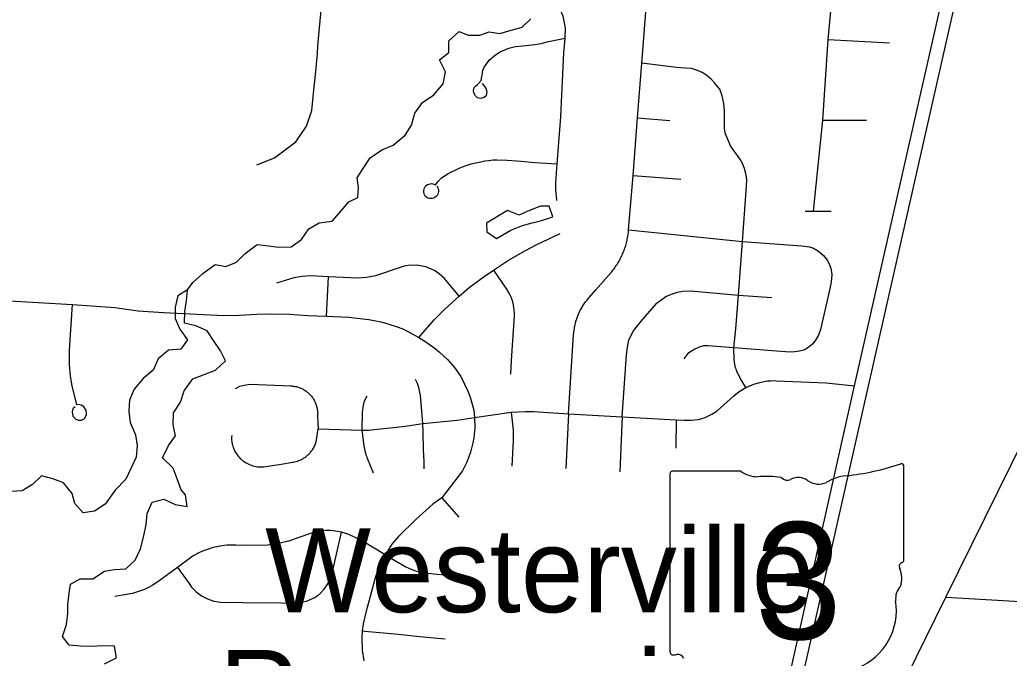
# Model space of a CAD drawing. Extents: x 0 to 34, y 0 to 22.
# Drawn here: x 8.488 to 9.603, y 8.895 to 9.615 of the extents above; entities that cross this region are included whole.
import ezdxf

# ---------------------------------------------------------------- set-up
doc = ezdxf.new("R2010")
doc.units = 0
for name, color, linetype in [('GM_X_County_Road', 7, 'Continuous'), ('GM_X_Minor_Lake', 7, 'Continuous'), ('GM_X_Minor_Lake_Text', 7, 'Continuous'), ('GM_X_Minor_River', 7, 'Continuous'), ('GM_X_Rail_Line', 7, 'Continuous'), ('GM_X_State_Location', 7, 'Continuous'), ('GM_X_State_Route', 7, 'Continuous'), ('GM_X_State_Shield', 7, 'Continuous'), ('GM_X_Township_Road', 7, 'Continuous')]:
    doc.layers.add(name, color=color, linetype=linetype)

msp = doc.modelspace()

# ---------------------------------------------------------------- linework, layer by layer
at = {"layer": 'GM_X_County_Road'}
msp.add_lwpolyline([(9.2983, 8.492), (9.3206, 8.5378), (9.4763, 8.8512), (9.532, 8.9642), (9.6643, 9.2319), (9.7654, 9.4338), (9.7887, 9.4806), (9.823, 9.5499), (9.8784, 9.6595), (9.9012, 9.7059), (9.9498, 9.7963), (10.0655, 10.0271), (10.1462, 10.1841)], dxfattribs=at)
at = {"layer": 'GM_X_Minor_Lake'}
for points in [[(9.0846, 9.3914), (9.0889, 9.3928), (9.0847, 9.4049), (9.0749, 9.4049), (9.0609, 9.3992), (9.0511, 9.3946), (9.0378, 9.3999)], [(9.0378, 9.3999), (9.014, 9.3858), (9.0144, 9.376), (9.0254, 9.3684), (9.0416, 9.3779), (9.0549, 9.3829), (9.0655, 9.3859), (9.0761, 9.3886), (9.0846, 9.3914)], [(8.6699, 9.0851), (8.6654, 9.0976), (8.661, 9.1098), (8.6489, 9.1212), (8.6558, 9.1352), (8.6635, 9.1462), (8.6609, 9.1583), (8.6613, 9.172), (8.669, 9.1841), (8.6732, 9.1969), (8.6831, 9.2101), (8.696, 9.215), (8.7086, 9.2199), (8.72, 9.2304), (8.7144, 9.2418), (8.7072, 9.2525), (8.6994, 9.2643), (8.6865, 9.27), (8.6737, 9.2731), (8.6742, 9.286), (8.6761, 9.2985), (8.677, 9.3106), (8.6663, 9.3039), (8.6632, 9.291), (8.6631, 9.2781), (8.6684, 9.2663), (8.677, 9.2542), (8.6694, 9.2436), (8.6557, 9.2425), (8.6439, 9.2327), (8.6382, 9.2202), (8.6272, 9.2108), (8.6169, 9.1988), (8.6115, 9.1863), (8.611, 9.1738), (8.6125, 9.1609), (8.6184, 9.1472), (8.6203, 9.135), (8.619, 9.1221), (8.6137, 9.11), (8.6075, 9.0972), (8.5954, 9.0847), (8.5843, 9.0689), (8.5721, 9.061), (8.5596, 9.0592), (8.5502, 9.0698), (8.5469, 9.0812), (8.5372, 9.093), (8.5251, 9.0976), (8.5126, 9.1011), (8.5023, 9.0913), (8.4906, 9.0842), (8.4777, 9.0835)], [(8.5836, 8.8892), (8.5972, 8.8959), (8.5947, 8.9092), (8.581, 8.9093), (8.5693, 8.9086), (8.5564, 8.909), (8.5436, 8.9102), (8.5361, 8.9201), (8.5407, 8.9334), (8.5423, 8.9459), (8.542, 8.9557), (8.5436, 8.9686), (8.5452, 8.9789), (8.5562, 8.9849), (8.5702, 8.9848), (8.5834, 8.9934), (8.5948, 8.9956), (8.6077, 8.996), (8.618, 9.0061), (8.6241, 9.0186), (8.628, 9.0334), (8.6303, 9.0463), (8.6315, 9.0584), (8.6373, 9.0712), (8.6505, 9.0746), (8.663, 9.0688), (8.6766, 9.0665), (8.6748, 9.0794), (8.6699, 9.0851)]]:
    msp.add_lwpolyline(points, dxfattribs=at)
at = {"layer": 'GM_X_Minor_River'}
msp.add_lwpolyline([(8.677, 9.3106), (8.683, 9.319), (8.6943, 9.3289), (8.7083, 9.3391), (8.7201, 9.3369), (8.7322, 9.3418), (8.742, 9.3517), (8.7556, 9.3616), (8.7688, 9.3601), (8.7791, 9.3586), (8.7938, 9.359), (8.8055, 9.3673), (8.8138, 9.3795), (8.8256, 9.3859), (8.8403, 9.3878), (8.8483, 9.3973), (8.8588, 9.4099), (8.8691, 9.4148), (8.8698, 9.4254), (8.8683, 9.4368), (8.8743, 9.4463), (8.883, 9.4592), (8.8962, 9.4683), (8.9091, 9.4736), (8.9223, 9.485), (8.9295, 9.496), (8.9333, 9.5097), (8.942, 9.5218), (8.9548, 9.5302), (8.9654, 9.5427), (8.968, 9.5564), (8.9612, 9.5696), (8.9718, 9.578), (8.9718, 9.5913), (8.9835, 9.6015), (8.9934, 9.5974), (9.0066, 9.5974), (9.0172, 9.6012), (9.0293, 9.5993), (9.0418, 9.6031), (9.0543, 9.6065), (9.0641, 9.616)], dxfattribs=at)
at = {"layer": 'GM_X_Rail_Line'}
msp.add_lwpolyline([(8.9712, 7.0765), (9.0871, 7.5941), (9.3068, 8.5932), (9.5523, 9.677), (9.6655, 10.1841)], dxfattribs=at)
at = {"layer": 'GM_X_State_Route'}
for points in [[(9.5019, 9.5239), (9.5372, 9.6798), (9.5642, 9.8016), (9.5722, 9.8371)], [(9.2639, 8.467), (9.2779, 8.5236), (9.3327, 8.7717), (9.3344, 8.7799), (9.4291, 9.2024), (9.5019, 9.5239)]]:
    msp.add_lwpolyline(points, dxfattribs=at)
at = {"layer": 'GM_X_State_Shield'}
for p, q in [((9.221, 9.1029), (9.221, 8.9028)), ((9.3008, 9.1064), (9.2236, 9.1064)), ((9.4847, 9.0066), (9.4847, 9.1113)), ((9.4846, 9.0067), (9.4847, 9.0066))]:
    msp.add_line(p, q, dxfattribs=at)
for centre, radius, start, end in [((9.3908, 9.3792), 0.2796, 275.8445, 288.9065), ((9.4817, 9.1118), 0.00294, 351.8621, 97.738), ((9.224, 9.1034), 0.00305, 98.1301, 188.1301), ((9.3192, 9.1296), 0.0296, 231.6195, 271.1119), ((9.329, 8.994), 0.1064, 80.4867, 94.9883), ((9.3532, 9.1044), 0.00855, 219.7921, 297.1024), ((9.3657, 9.0813), 0.0178, 54.4667, 119.1411), ((9.3887, 9.113), 0.0214, 233.8562, 294.8282), ((9.4264, 9.0453), 0.0563, 97.3462, 120.7689), ((9.484, 8.999), 0.00454, 107.944, 210.337), ((9.4815, 9.0062), 0.00314, 289.6038, 7.7341), ((9.4551, 8.9857), 0.0273, 340.033, 23.6496), ((9.4952, 8.9628), 0.0198, 136.8065, 186.9296), ((9.4064, 8.9495), 0.0699, 292.3089, 8.9858), ((9.2241, 8.9024), 0.00308, 171.9584, 258.3066), ((9.2245, 8.9228), 0.0235, 267.339, 280.6039), ((9.2293, 8.8913), 0.00848, 29.7484, 93.2717)]:
    msp.add_arc(centre, radius, start, end, dxfattribs=at)
at = {"layer": 'GM_X_Township_Road'}
for p, q in [((9.3993, 9.5927), (9.4687, 9.5889)), ((9.1843, 9.5044), (9.2209, 9.5015)), ((9.3934, 9.5017), (9.4424, 9.5017)), ((9.1794, 9.4396), (9.2332, 9.4354)), ((8.8338, 9.281), (8.8362, 9.3253)), ((9.2981, 9.3047), (9.3359, 9.302)), ((9.0007, 9.1666), (9.0421, 9.1726)), ((9.1068, 9.1708), (9.1035, 9.1094)), ((9.1672, 9.1673), (9.1645, 9.1054)), ((9.2279, 9.164), (9.2277, 9.132)), ((8.9639, 9.076), (8.9829, 9.0543)), ((9.532, 8.9642), (9.7974, 8.9489))]:
    msp.add_line(p, q, dxfattribs=at)
for points in [[(8.8217, 9.5567), (8.8237, 9.577), (8.824, 9.585), (8.8259, 9.6059), (8.8282, 9.6294), (8.8286, 9.6401), (8.8313, 9.6621), (8.8324, 9.6781), (8.8372, 9.7213)], [(9.0977, 9.5008), (9.0981, 9.5058), (9.1015, 9.5777), (9.1028, 9.5942), (9.1033, 9.606), (9.1007, 9.6191), (9.0959, 9.63), (9.0902, 9.6453), (9.0858, 9.6619), (9.0845, 9.6754), (9.0854, 9.6924), (9.086, 9.7066)], [(9.3829, 9.3994), (9.3934, 9.5017), (9.3993, 9.5927), (9.4084, 9.6884)], [(9.1068, 9.1708), (9.1122, 9.2597), (9.1133, 9.2679), (9.115, 9.2748), (9.1169, 9.28), (9.1184, 9.2844), (9.1189, 9.2856), (9.1195, 9.2868), (9.1202, 9.2879), (9.1208, 9.2891), (9.1215, 9.2902), (9.1221, 9.2914), (9.1228, 9.2925), (9.1236, 9.2936), (9.1243, 9.2947), (9.1251, 9.2958), (9.1258, 9.2969), (9.1266, 9.2979), (9.1275, 9.299), (9.1283, 9.3), (9.1291, 9.301), (9.13, 9.302), (9.1376, 9.3106), (9.1543, 9.3296), (9.1553, 9.3308), (9.1562, 9.3319), (9.1571, 9.3331), (9.158, 9.3343), (9.1589, 9.3355), (9.1597, 9.3367), (9.1605, 9.3379), (9.1613, 9.3392), (9.1621, 9.3405), (9.1629, 9.3417), (9.1636, 9.343), (9.1643, 9.3443), (9.165, 9.3456), (9.1657, 9.3469), (9.1664, 9.3483), (9.167, 9.3496), (9.1676, 9.351), (9.1682, 9.3523), (9.1687, 9.3537), (9.1693, 9.3551), (9.1698, 9.3565), (9.1702, 9.3579), (9.1707, 9.3593), (9.1711, 9.3607), (9.1715, 9.3621), (9.1719, 9.3636), (9.1723, 9.365), (9.1726, 9.3665), (9.1729, 9.3679), (9.1732, 9.3694), (9.1735, 9.3708), (9.1737, 9.3723), (9.1739, 9.3738), (9.1741, 9.375), (9.1744, 9.3783), (9.1794, 9.4396), (9.1843, 9.5044), (9.1892, 9.566), (9.1964, 9.6572)], [(9.0095, 9.5546), (9.0098, 9.5566), (9.0111, 9.5609), (9.017, 9.5694), (9.0242, 9.5752), (9.0296, 9.5787), (9.0392, 9.583), (9.0468, 9.5847), (9.0549, 9.5855), (9.0658, 9.5868), (9.0758, 9.5881), (9.0841, 9.5903), (9.1028, 9.5942)], [(9.3064, 9.2005), (9.3, 9.2112), (9.2964, 9.2188), (9.2947, 9.224), (9.2935, 9.2322), (9.2932, 9.2454), (9.2951, 9.2668), (9.2981, 9.3047), (9.3026, 9.365), (9.307, 9.4223), (9.3077, 9.4337), (9.3072, 9.4378), (9.3065, 9.4418), (9.3049, 9.4472), (9.303, 9.4522), (9.3006, 9.457), (9.2972, 9.4618), (9.2928, 9.4681), (9.2893, 9.473), (9.2865, 9.4791), (9.2833, 9.487), (9.2825, 9.4927), (9.2824, 9.5018), (9.2826, 9.5122), (9.2818, 9.5207), (9.2799, 9.529), (9.2771, 9.5366), (9.2745, 9.5397), (9.2712, 9.5438), (9.2678, 9.5476), (9.2625, 9.5522), (9.2572, 9.5553), (9.2519, 9.5579), (9.2451, 9.5599), (9.2382, 9.5605), (9.2284, 9.5613), (9.1892, 9.566)], [(8.8189, 9.528), (8.82, 9.5393), (8.8217, 9.5567)], [(9.0094, 9.5432), (9.0135, 9.538), (9.0146, 9.5336), (9.0138, 9.5292), (9.0115, 9.5274), (9.0077, 9.5263), (9.0041, 9.5269), (9.0016, 9.5291), (8.9998, 9.5324), (8.9995, 9.535), (9.0003, 9.5384), (9.0016, 9.5401), (9.0039, 9.5418), (9.008, 9.5466), (9.0095, 9.5546)], [(8.7554, 9.4515), (8.7753, 9.4592), (8.7992, 9.4775), (8.8114, 9.4951), (8.8174, 9.5128), (8.8189, 9.528)], [(9.0934, 9.4111), (9.0924, 9.4231), (9.0922, 9.43), (9.0926, 9.4368), (9.0939, 9.4524), (9.0977, 9.5008)], [(8.9582, 9.4274), (8.9591, 9.4261), (8.9597, 9.4246), (8.96, 9.423), (8.9601, 9.4214), (8.9598, 9.4198), (8.9592, 9.4183), (8.9584, 9.4169), (8.9573, 9.4157), (8.956, 9.4147), (8.9545, 9.414), (8.953, 9.4135), (8.9514, 9.4134), (8.9498, 9.4136), (8.9482, 9.414), (8.9468, 9.4147), (8.9463, 9.4152), (8.9452, 9.4163), (8.9443, 9.4177), (8.9437, 9.4192), (8.9434, 9.4208), (8.9434, 9.4224), (8.9437, 9.424), (8.9443, 9.4255), (8.9452, 9.4269), (8.9463, 9.4281), (8.9476, 9.4291), (8.949, 9.4298), (8.9506, 9.4302), (8.9522, 9.4303), (8.9538, 9.4301), (8.9568, 9.4289), (8.9592, 9.4324), (8.9633, 9.4368), (8.9717, 9.442), (8.9819, 9.447), (8.9859, 9.4487), (8.9913, 9.4507), (8.9968, 9.4524), (9.0023, 9.4538), (9.0079, 9.4549), (9.0122, 9.4558), (9.0167, 9.4565), (9.0189, 9.4567), (9.0212, 9.4569), (9.0258, 9.457), (9.0373, 9.4567), (9.0531, 9.4555), (9.0685, 9.4542), (9.0939, 9.4524)], [(9.3733, 9.3994), (9.3829, 9.3994), (9.4026, 9.3994)], [(8.9379, 9.2569), (8.9552, 9.2768), (8.967, 9.2887), (8.9832, 9.3035), (8.9948, 9.3133), (9.0114, 9.3256), (9.022, 9.3328), (9.0391, 9.3439), (9.0581, 9.3548), (9.071, 9.3615), (9.0972, 9.3741)], [(9.1744, 9.3783), (9.3026, 9.365), (9.3696, 9.3602), (9.3784, 9.3592), (9.3828, 9.3575), (9.3883, 9.3543), (9.394, 9.3494), (9.3988, 9.3437), (9.401, 9.3387), (9.4023, 9.3349), (9.4036, 9.328), (9.4031, 9.3229), (9.4024, 9.3172), (9.4004, 9.3086), (9.3979, 9.2972), (9.3909, 9.2658), (9.3883, 9.2595), (9.385, 9.2538), (9.3819, 9.2498), (9.3785, 9.2469), (9.3732, 9.2428), (9.3672, 9.2416), (9.3619, 9.2407), (9.3566, 9.2402), (9.3412, 9.2415), (9.2932, 9.2454)], [(8.9832, 9.3035), (8.9667, 9.3232), (8.9608, 9.3286), (8.9555, 9.3322), (8.9457, 9.3364), (8.9352, 9.3383), (8.926, 9.338), (8.9214, 9.3372), (8.9169, 9.3359), (8.8891, 9.3264), (8.8787, 9.3243), (8.8691, 9.3238), (8.8362, 9.3253), (8.816, 9.3262), (8.8062, 9.3257), (8.7969, 9.324), (8.7774, 9.318)], [(9.022, 9.3328), (9.0373, 9.3103), (9.0391, 9.3074), (9.0404, 9.3049), (9.0415, 9.3026), (9.0426, 9.2997), (9.0437, 9.2961), (9.0444, 9.293), (9.0451, 9.2883), (9.0453, 9.2839), (9.0453, 9.2811), (9.0421, 9.2311), (9.0411, 9.2156)], [(9.1672, 9.1673), (9.1719, 9.2372), (9.173, 9.246), (9.1747, 9.2541), (9.1799, 9.2645), (9.1904, 9.2774), (9.2067, 9.2959), (9.2106, 9.2991), (9.2162, 9.3031), (9.2226, 9.3058), (9.2295, 9.3081), (9.2356, 9.3091), (9.2446, 9.3094), (9.2981, 9.3047)], [(8.4505, 9.2997), (8.5475, 9.2942), (8.595, 9.2906), (8.6214, 9.287), (8.6501, 9.285), (8.6877, 9.2831), (8.7179, 9.2817), (8.7355, 9.2819), (8.7554, 9.2831), (8.7715, 9.2834), (8.7923, 9.283), (8.8126, 9.2818), (8.8338, 9.281), (8.8588, 9.2796), (8.8815, 9.2773), (8.895, 9.2746), (8.9017, 9.2728), (8.9147, 9.2684), (8.9204, 9.2661), (8.927, 9.2629), (8.9379, 9.2569), (8.9458, 9.2519), (8.9564, 9.2443), (8.9612, 9.2405), (8.9701, 9.2322), (8.9782, 9.223), (8.9853, 9.2131), (8.9936, 9.1958), (8.9958, 9.1898), (8.9998, 9.1751), (9.0007, 9.1666), (9.0009, 9.1549), (8.9999, 9.1438), (8.9989, 9.1383), (8.9961, 9.1275), (8.9921, 9.1165), (8.9872, 9.1067), (8.9639, 9.076), (8.9536, 9.069), (8.9346, 9.0516), (8.915, 9.0326), (8.9076, 9.0239), (8.9, 9.0121), (8.8932, 8.9986), (8.8891, 8.987), (8.8784, 8.9484), (8.8751, 8.9342), (8.8741, 8.9266), (8.8735, 8.9176), (8.8741, 8.9046), (8.8757, 8.8926)], [(8.5506, 9.1787), (8.5477, 9.1764), (8.5469, 9.1732), (8.5479, 9.1684), (8.5499, 9.1658), (8.5512, 9.1648), (8.5543, 9.1636), (8.5576, 9.1636), (8.5608, 9.1656), (8.5632, 9.1699), (8.563, 9.1748), (8.5603, 9.1789), (8.5575, 9.1806), (8.5542, 9.1812), (8.5523, 9.1809), (8.5472, 9.2023), (8.5453, 9.2133), (8.5441, 9.2262), (8.5441, 9.2424), (8.5475, 9.2942)], [(9.2932, 9.2454), (9.2642, 9.2475), (9.2587, 9.2473), (9.2538, 9.246), (9.249, 9.2437), (9.2413, 9.2388), (9.2367, 9.2327)], [(8.7311, 9.1993), (8.7361, 9.2019), (8.7408, 9.2033), (8.7478, 9.2043), (8.793, 9.2025), (8.7947, 9.2024), (8.7958, 9.2022), (8.797, 9.2021), (8.7981, 9.2018), (8.7998, 9.2015), (8.8009, 9.2012), (8.802, 9.2008), (8.8037, 9.2002), (8.8047, 9.1998), (8.8058, 9.1993), (8.8073, 9.1985), (8.8083, 9.198), (8.8093, 9.1974), (8.8107, 9.1964), (8.8121, 9.1954), (8.8129, 9.1947), (8.8142, 9.1935), (8.815, 9.1927), (8.8162, 9.1915), (8.8169, 9.1906), (8.8176, 9.1897), (8.8183, 9.1888), (8.8192, 9.1873), (8.8198, 9.1863), (8.8203, 9.1853), (8.8208, 9.1843), (8.8215, 9.1828), (8.8219, 9.1817), (8.8223, 9.1806), (8.8226, 9.1795), (8.8229, 9.1784), (8.8232, 9.1773), (8.8234, 9.1761), (8.8236, 9.175), (8.8237, 9.1739), (8.8238, 9.1727), (8.8239, 9.171), (8.8238, 9.1698), (8.8238, 9.1686), (8.8243, 9.154)], [(8.9424, 9.1599), (8.9412, 9.1736), (8.9396, 9.192), (8.938, 9.2004), (8.9364, 9.2049), (8.9343, 9.2096)], [(9.0421, 9.1726), (9.0581, 9.1736), (9.067, 9.1736), (9.1068, 9.1708), (9.1672, 9.1673), (9.2279, 9.164), (9.2371, 9.1636), (9.2448, 9.1637), (9.253, 9.1646), (9.2608, 9.1668), (9.2681, 9.1703), (9.2741, 9.1743), (9.293, 9.1911), (9.2989, 9.1959), (9.3064, 9.2005), (9.3155, 9.2043), (9.3222, 9.2063), (9.3274, 9.2074), (9.3311, 9.2079), (9.3347, 9.2082), (9.3384, 9.2083), (9.3407, 9.2082), (9.397, 9.2058), (9.4291, 9.2024)], [(8.874, 9.1526), (8.8742, 9.1722), (8.8751, 9.1785), (8.8767, 9.1855), (8.8796, 9.1913)], [(9.0421, 9.1726), (9.0441, 9.1523), (9.0444, 9.1407), (9.0429, 9.112)], [(8.8243, 9.154), (8.874, 9.1526), (8.8757, 9.1525), (8.8786, 9.1525), (8.8816, 9.1526), (8.8846, 9.1528), (8.8873, 9.1531), (8.9097, 9.1554), (8.9251, 9.1575), (8.9424, 9.1599), (8.981, 9.1637), (9.0007, 9.1666)], [(8.9439, 9.1088), (8.9437, 9.1167), (8.943, 9.1308), (8.9429, 9.1497), (8.9424, 9.1599)], [(8.7269, 9.1466), (8.7267, 9.1446), (8.7267, 9.1429), (8.7268, 9.1412), (8.727, 9.1395), (8.7272, 9.1384), (8.7274, 9.1373), (8.7278, 9.1357), (8.7282, 9.134), (8.7288, 9.1324), (8.7292, 9.1314), (8.7306, 9.1283), (8.7322, 9.1259), (8.7332, 9.1245), (8.7342, 9.1232), (8.7353, 9.1219), (8.7365, 9.1206), (8.7374, 9.1198), (8.7382, 9.1191), (8.7396, 9.118), (8.741, 9.117), (8.7424, 9.116), (8.7439, 9.1152), (8.7455, 9.1144), (8.7471, 9.1137), (8.7487, 9.113), (8.7498, 9.1126), (8.7509, 9.1123), (8.7526, 9.1119), (8.7543, 9.1115), (8.756, 9.1112), (8.7578, 9.1111), (8.7595, 9.111), (8.7613, 9.111), (8.7631, 9.1111), (8.7849, 9.1144), (8.7937, 9.116), (8.795, 9.1162), (8.7961, 9.1163), (8.7978, 9.1167), (8.7994, 9.1171), (8.801, 9.1176), (8.8025, 9.1181), (8.8041, 9.1188), (8.8056, 9.1195), (8.8071, 9.1203), (8.8084, 9.1212), (8.8094, 9.1218), (8.8103, 9.1224), (8.812, 9.1238), (8.8129, 9.1245), (8.8137, 9.1253), (8.8152, 9.1269), (8.8159, 9.1277), (8.8166, 9.1286), (8.8179, 9.1303), (8.819, 9.1322), (8.82, 9.1341), (8.8209, 9.1359), (8.8216, 9.1379), (8.8222, 9.1398), (8.8226, 9.1417), (8.8243, 9.154)], [(8.8869, 9.104), (8.8801, 9.1206), (8.8798, 9.1213), (8.8795, 9.122), (8.8793, 9.1227), (8.879, 9.1234), (8.8788, 9.1241), (8.8785, 9.1249), (8.8783, 9.1256), (8.8781, 9.1263), (8.8779, 9.1271), (8.8777, 9.1278), (8.8775, 9.1286), (8.8773, 9.1293), (8.8772, 9.13), (8.877, 9.1308), (8.8769, 9.1315), (8.8768, 9.1323), (8.8766, 9.133), (8.8765, 9.1338), (8.8764, 9.1346), (8.874, 9.1526)], [(8.9, 9.0121), (8.8731, 9.0282), (8.8588, 9.0349), (8.8507, 9.0375), (8.8462, 9.0384), (8.8418, 9.039), (8.8374, 9.0392), (8.8331, 9.0392), (8.8287, 9.0389), (8.8192, 9.0372), (8.8014, 9.0313), (8.7912, 9.0274), (8.7794, 9.0246), (8.7673, 9.023), (8.742, 9.0226), (8.7314, 9.0229), (8.7213, 9.0227), (8.7162, 9.0221), (8.706, 9.0201), (8.6962, 9.017), (8.6914, 9.015), (8.6833, 9.0108), (8.6657, 8.9975), (8.645, 8.9828), (8.6412, 8.98), (8.6371, 8.9774), (8.633, 8.9751), (8.6287, 8.973), (8.6197, 8.9697), (8.6151, 8.9685), (8.6082, 8.9673), (8.595, 8.9651)], [(8.6657, 8.9975), (8.6788, 8.9798), (8.6815, 8.9757), (8.6868, 8.9703), (8.6929, 8.9657), (8.6996, 8.9622), (8.7068, 8.9598), (8.7143, 8.9586), (8.7393, 8.9583), (8.7825, 8.9577), (8.7988, 8.9576), (8.8111, 8.9596), (8.8207, 8.9639), (8.8264, 8.9681), (8.8312, 8.9732), (8.8352, 8.9791), (8.8375, 8.9841), (8.8405, 8.9927), (8.8507, 9.0375)], [(8.9, 9.0121), (8.9233, 8.9986), (8.9265, 8.9968), (8.9347, 8.9935), (8.9419, 8.992), (8.958, 8.99), (8.9731, 8.9891)], [(8.8741, 8.9266), (8.8769, 8.9261), (8.8938, 8.9246), (8.9146, 8.9224), (8.9391, 8.9199), (8.9675, 8.9172)]]:
    msp.add_lwpolyline(points, dxfattribs=at)

# ---------------------------------------------------------------- texts
at = {"layer": 'GM_X_Minor_Lake_Text'}
for s, rotation, p in [('Westerville', 359.9957, (8.7645, 8.9473)), ('Reservoir', 359.9946, (8.7126, 8.81))]:
    msp.add_text(s, height=0.09469, rotation=rotation, dxfattribs=at).set_placement(p)
at = {"layer": 'GM_X_State_Location'}
for s in ['s', 'r']:
    msp.add_text(s, height=0.000189, dxfattribs=at).set_placement((9.3499, 8.9896))
msp.add_text('3', height=0.000189, rotation=0, dxfattribs=at).set_placement((9.3213, 8.9758))
at = {"layer": 'GM_X_State_Shield'}
msp.add_text('3', height=0.1318, dxfattribs=at).set_placement((9.3167, 8.9169))

doc.saveas('drawing.dxf')
